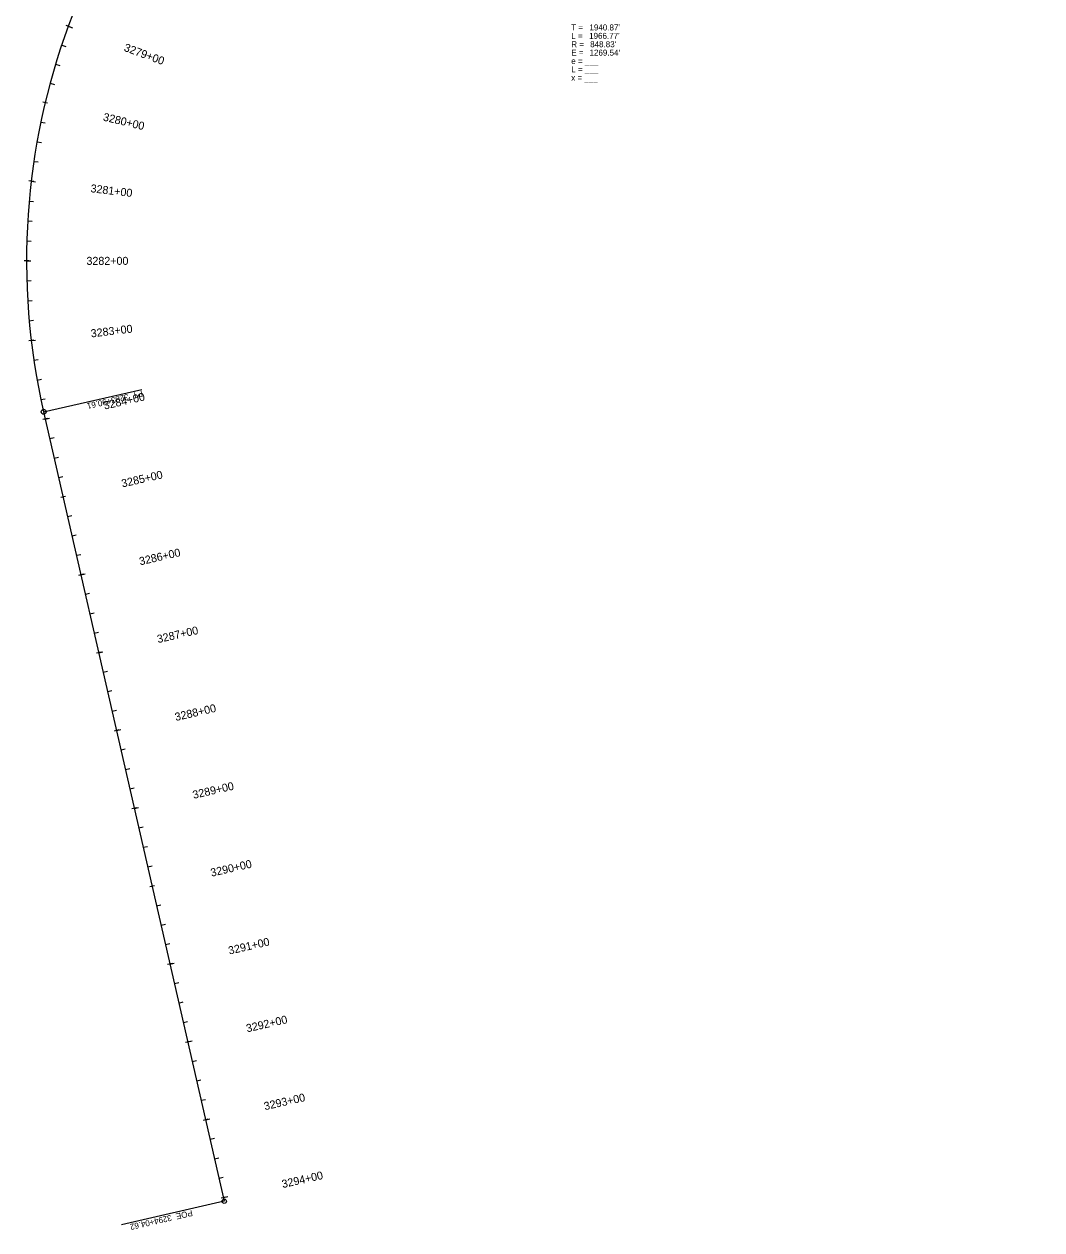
# Model space of a CAD drawing. Extents: x 15451313 to 15455081, y 8857737 to 8860760.
# Drawn here: x 15451800 to 15453075, y 8857737 to 8859247 of the extents above; entities that cross this region are included whole.
import ezdxf

# ---------------------------------------------------------------- set-up
doc = ezdxf.new("R2010")
doc.units = 0
for name, color, linetype in [('Annotation', 7, 'Continuous'), ('PC_REVISION_ANNOTATION', 7, 'Continuous'), ('SheetAddenda', 7, 'Continuous'), ('TextNonPlot', 7, 'Continuous')]:
    doc.layers.add(name, color=color, linetype=linetype)

msp = doc.modelspace()

# ---------------------------------------------------------------- linework, layer by layer
at = {"layer": 'Annotation'}
msp.add_line((15451824.5, 8858761.5), (15452050.7, 8857773), dxfattribs=at)
msp.add_arc((15452651.9, 8858950.9), 848.8, 60.1345, 192.8906, dxfattribs=at)
at = {"layer": 'PC_REVISION_ANNOTATION'}
for p, q in [((15451858.3, 8859243.3), (15451852.6, 8859245.4)), ((15451847.1, 8859220.7), (15451852.3, 8859219)), ((15451839.5, 8859196.9), (15451844.8, 8859195.3)), ((15451832.6, 8859172.9), (15451837.9, 8859171.5)), ((15451829.4, 8859148), (15451823.5, 8859149.4)), ((15451821, 8859124.3), (15451826.3, 8859123.2)), ((15451816.2, 8859099.7), (15451821.6, 8859098.8)), ((15451812.2, 8859075.1), (15451817.6, 8859074.3)), ((15451812, 8859049.9), (15451805.9, 8859050.6)), ((15451806.4, 8859025.4), (15451811.8, 8859024.9)), ((15451804.5, 8859000.5), (15451810, 8859000.2)), ((15451803.4, 8858975.5), (15451808.9, 8858975.3)), ((15451806.1, 8858950.5), (15451800, 8858950.5)), ((15451803.5, 8858925.5), (15451808.9, 8858925.7)), ((15451804.6, 8858900.5), (15451810, 8858900.9)), ((15451806.4, 8858875.6), (15451811.9, 8858876.1)), ((15451812, 8858851.1), (15451806, 8858850.4)), ((15451812.3, 8858826), (15451817.7, 8858826.8)), ((15451816.4, 8858801.3), (15451821.7, 8858802.2)), ((15451821.1, 8858776.7), (15451826.5, 8858777.9)), ((15451829.6, 8858753), (15451823.6, 8858751.7)), ((15451832.1, 8858728), (15451837.5, 8858729.2)), ((15451837.7, 8858703.6), (15451843, 8858704.8)), ((15451843.3, 8858679.2), (15451848.6, 8858680.5)), ((15451851.9, 8858655.5), (15451845.9, 8858654.2)), ((15451854.5, 8858630.5), (15451859.8, 8858631.7)), ((15451860, 8858606.1), (15451865.4, 8858607.3)), ((15451865.6, 8858581.8), (15451870.9, 8858583)), ((15451874.2, 8858558.1), (15451868.2, 8858556.7)), ((15451876.8, 8858533), (15451882.1, 8858534.2)), ((15451882.3, 8858508.6), (15451887.7, 8858509.9)), ((15451887.9, 8858484.3), (15451893.2, 8858485.5)), ((15451896.5, 8858460.6), (15451890.5, 8858459.2)), ((15451899.1, 8858435.5), (15451904.4, 8858436.8)), ((15451904.7, 8858411.2), (15451910, 8858412.4)), ((15451910.2, 8858386.8), (15451915.6, 8858388)), ((15451918.8, 8858363.1), (15451912.8, 8858361.7)), ((15451921.4, 8858338.1), (15451926.7, 8858339.3)), ((15451927, 8858313.7), (15451932.3, 8858314.9)), ((15451932.5, 8858289.3), (15451937.9, 8858290.5)), ((15451941.1, 8858265.6), (15451935.1, 8858264.3)), ((15451943.7, 8858240.6), (15451949, 8858241.8)), ((15451949.3, 8858216.2), (15451954.6, 8858217.4)), ((15451954.8, 8858191.8), (15451960.2, 8858193.1)), ((15451963.4, 8858168.1), (15451957.4, 8858166.8)), ((15451966, 8858143.1), (15451971.3, 8858144.3)), ((15451971.6, 8858118.7), (15451976.9, 8858119.9)), ((15451977.2, 8858094.4), (15451982.5, 8858095.6)), ((15451985.7, 8858070.7), (15451979.8, 8858069.3)), ((15451988.3, 8858045.6), (15451993.6, 8858046.8)), ((15451993.9, 8858021.2), (15451999.2, 8858022.5)), ((15451999.5, 8857996.9), (15452004.8, 8857998.1)), ((15452008, 8857973.2), (15452002.1, 8857971.8)), ((15452010.6, 8857948.1), (15452015.9, 8857949.4)), ((15452016.2, 8857923.8), (15452021.5, 8857925)), ((15452021.8, 8857899.4), (15452027.1, 8857900.6)), ((15452030.3, 8857875.7), (15452024.4, 8857874.3)), ((15452032.9, 8857850.7), (15452038.3, 8857851.9)), ((15452038.5, 8857826.3), (15452043.8, 8857827.5)), ((15452044.1, 8857801.9), (15452049.4, 8857803.1)), ((15452052.6, 8857778.2), (15452046.7, 8857776.9))]:
    msp.add_line(p, q, dxfattribs=at)
at = {"layer": 'SheetAddenda'}
for p, q in [((15451855.4, 8859244.3), (15451860.5, 8859242.4)), ((15451829.4, 8859148), (15451823.5, 8859149.4)), ((15451808.9, 8859050.3), (15451814.3, 8859049.6)), ((15451803.1, 8858950.5), (15451808.5, 8858950.5)), ((15451809, 8858850.7), (15451814.4, 8858851.4)), ((15451826.6, 8858752.3), (15451831.9, 8858753.6)), ((15451851.9, 8858655.5), (15451845.9, 8858654.2)), ((15451871.2, 8858557.4), (15451876.5, 8858558.6)), ((15451893.5, 8858459.9), (15451898.8, 8858461.1)), ((15451915.8, 8858362.4), (15451921.1, 8858363.6)), ((15451938.1, 8858264.9), (15451943.4, 8858266.2)), ((15451963.4, 8858168.1), (15451957.4, 8858166.8)), ((15451982.7, 8858070), (15451988.1, 8858071.2)), ((15452005, 8857972.5), (15452010.4, 8857973.7)), ((15452027.4, 8857875), (15452032.7, 8857876.2)), ((15452049.7, 8857777.5), (15452055, 8857778.8))]:
    msp.add_line(p, q, dxfattribs=at)
at = {"layer": 'TextNonPlot'}
for p, q in [((15451824.5, 8858761.5), (15451947.3, 8858789.6)), ((15451947.3, 8858789.6), (15451947.3, 8858789.6)), ((15452050.7, 8857773), (15451922, 8857743.6)), ((15451922, 8857743.6), (15451922, 8857743.6))]:
    msp.add_line(p, q, dxfattribs=at)
for centre, radius in [((15451824.5, 8858761.5), 3.12), ((15452050.7, 8857773), 2.67)]:
    msp.add_circle(centre, radius, dxfattribs=at)

# ---------------------------------------------------------------- texts
at = {"layer": 'PC_REVISION_ANNOTATION'}
for s, rotation, p in [('3279+00', 339.7743, (15451924.1, 8859213.7)), ('3280+00', 346.5243, (15451898.2, 8859126.3)), ('3281+00', 353.2743, (15451882.8, 8859036.5)), ('3282+00', 0.0242, (15451878.1, 8858945.5)), ('3283+00', 6.7742, (15451884.1, 8858854.6)), ('3284+00', 12.8906, (15451900.8, 8858764.2)), ('3285+00', 12.8906, (15451923.1, 8858666.7)), ('3286+00', 12.8906, (15451945.4, 8858569.2)), ('3287+00', 12.8906, (15451967.7, 8858471.8)), ('3288+00', 12.8906, (15451990, 8858374.3)), ('3289+00', 12.8906, (15452012.3, 8858276.8)), ('3290+00', 12.8906, (15452034.7, 8858179.3)), ('3291+00', 12.8906, (15452057, 8858081.8)), ('3292+00', 12.8906, (15452079.3, 8857984.4)), ('3293+00', 12.8906, (15452101.6, 8857886.9)), ('3294+00', 12.8906, (15452123.9, 8857789.4))]:
    msp.add_text(s, height=10.02, rotation=rotation, dxfattribs=at).set_placement(p)
at = {"layer": 'SheetAddenda'}
for s, rotation, p in [('3280+00', 346.5243, (15451898.2, 8859126.3)), ('3285+00', 12.8906, (15451923.1, 8858666.7)), ('3290+00', 12.8906, (15452034.7, 8858179.3))]:
    msp.add_text(s, height=10.02, rotation=rotation, dxfattribs=at).set_placement(p)
at = {"layer": 'TextNonPlot'}
for s, p in [('T = ', (15452485.2, 8859239)), ("1940.87'", (15452508, 8859239)), ('L = ', (15452485.2, 8859228.5)), ("1966.77'", (15452507.6, 8859228.5)), ('R = ', (15452485.2, 8859218)), ("848.83'", (15452508.9, 8859218)), ('e = ___ ', (15452485.2, 8859197)), ('E = ', (15452485.2, 8859207.5)), ("1269.54'", (15452508.1, 8859207.5)), ('L = ___', (15452485.2, 8859186.5)), ('x = ___', (15452485.2, 8859176))]:
    msp.add_text(s, height=7.5, dxfattribs=at).set_placement(p)
for s, p in [('3283+90.61', (15451930, 8858784)), ('PT', (15451947.7, 8858788)), ('3294+04.62', (15451983.9, 8857756.1)), ('POE ', (15452010.1, 8857762.1))]:
    msp.add_text(s, height=7.5, rotation=192.8906, dxfattribs=at).set_placement(p)

doc.saveas('drawing.dxf')
